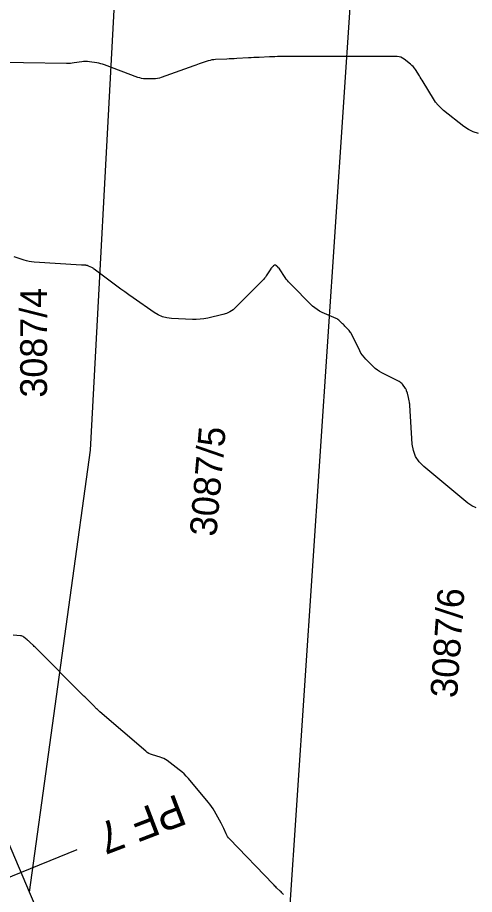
# Model space of a CAD drawing. Extents: x -534410 to -534262, y -1190162 to -1189584.
# Drawn here: x -534333.9 to -534319.42, y -1189974.68 to -1189946.91 of the extents above; entities that cross this region are included whole.
import ezdxf

# ---------------------------------------------------------------- set-up
doc = ezdxf.new("R2010")
doc.units = 0
for name, color, linetype in [('30', 7, 'Continuous'), ('31', 7, 'Continuous'), ('_N_text', 7, 'Continuous'), ('Hranice parcel', 7, 'Continuous'), ('Parcelní čísla', 7, 'Continuous')]:
    doc.layers.add(name, color=color, linetype=linetype)

msp = doc.modelspace()

# ---------------------------------------------------------------- linework, layer by layer
at = {"layer": '30'}
for points in [[(-534319.294, -1189950.581), (-534319.457, -1189950.53), (-534319.611, -1189950.455), (-534319.755, -1189950.356), (-534320.397, -1189949.847), (-534320.49, -1189949.766), (-534320.575, -1189949.678), (-534320.651, -1189949.583), (-534320.72, -1189949.48), (-534321.045, -1189948.943), (-534321.075, -1189948.894), (-534321.106, -1189948.845), (-534321.136, -1189948.796), (-534321.167, -1189948.747), (-534321.291, -1189948.552), (-534321.324, -1189948.505), (-534321.36, -1189948.461), (-534321.4, -1189948.42), (-534321.443, -1189948.382), (-534321.646, -1189948.221), (-534321.696, -1189948.187), (-534321.75, -1189948.163), (-534321.807, -1189948.148), (-534321.868, -1189948.144), (-534322.369, -1189948.144), (-534322.594, -1189948.144), (-534322.967, -1189948.144), (-534323.192, -1189948.144), (-534323.568, -1189948.144), (-534323.743, -1189948.144), (-534323.918, -1189948.144), (-534324.369, -1189948.144), (-534324.594, -1189948.144), (-534324.967, -1189948.144), (-534325.192, -1189948.144), (-534325.575, -1189948.144), (-534325.659, -1189948.144), (-534325.743, -1189948.146), (-534325.827, -1189948.148), (-534325.911, -1189948.151), (-534326.245, -1189948.167), (-534326.329, -1189948.171), (-534326.413, -1189948.175), (-534326.496, -1189948.179), (-534326.58, -1189948.184), (-534326.953, -1189948.204), (-534327.032, -1189948.208), (-534327.111, -1189948.212), (-534327.19, -1189948.216), (-534327.269, -1189948.22), (-534327.624, -1189948.237), (-534327.683, -1189948.241), (-534327.742, -1189948.25), (-534327.799, -1189948.263), (-534327.857, -1189948.279), (-534328.083, -1189948.354), (-534328.14, -1189948.372), (-534328.197, -1189948.392), (-534328.253, -1189948.411), (-534328.309, -1189948.431), (-534329.344, -1189948.802), (-534329.404, -1189948.821), (-534329.465, -1189948.834), (-534329.527, -1189948.842), (-534329.589, -1189948.845), (-534329.841, -1189948.845), (-534329.904, -1189948.842), (-534329.966, -1189948.834), (-534330.026, -1189948.82), (-534330.086, -1189948.801), (-534331.147, -1189948.405), (-534331.205, -1189948.386), (-534331.263, -1189948.369), (-534331.322, -1189948.355), (-534331.382, -1189948.344), (-534331.623, -1189948.306), (-534331.683, -1189948.299), (-534331.743, -1189948.297), (-534331.803, -1189948.299), (-534331.863, -1189948.306), (-534332.104, -1189948.344), (-534332.165, -1189948.352), (-534332.225, -1189948.358), (-534332.286, -1189948.361), (-534332.347, -1189948.361), (-534335.078, -1189948.316)], [(-534325.469, -1189974.679), (-534325.496, -1189974.652), (-534325.523, -1189974.624), (-534325.55, -1189974.597), (-534325.578, -1189974.571), (-534325.688, -1189974.463), (-534325.715, -1189974.436), (-534325.743, -1189974.409), (-534325.77, -1189974.382), (-534325.796, -1189974.354), (-534327.184, -1189972.912), (-534327.214, -1189972.877), (-534327.242, -1189972.84), (-534327.266, -1189972.801), (-534327.287, -1189972.759), (-534327.363, -1189972.588), (-534327.383, -1189972.546), (-534327.403, -1189972.504), (-534327.425, -1189972.462), (-534327.447, -1189972.421), (-534327.658, -1189972.04), (-534327.702, -1189971.964), (-534327.75, -1189971.89), (-534327.801, -1189971.819), (-534327.856, -1189971.75), (-534328.484, -1189970.999), (-534328.55, -1189970.924), (-534328.621, -1189970.853), (-534328.696, -1189970.787), (-534328.775, -1189970.724), (-534329.161, -1189970.438), (-534329.213, -1189970.403), (-534329.267, -1189970.373), (-534329.323, -1189970.348), (-534329.382, -1189970.327), (-534329.623, -1189970.256), (-534329.681, -1189970.235), (-534329.737, -1189970.209), (-534329.789, -1189970.176), (-534329.838, -1189970.138), (-534331.288, -1189968.891), (-534331.314, -1189968.867), (-534331.34, -1189968.843), (-534331.366, -1189968.819), (-534331.391, -1189968.794), (-534331.49, -1189968.692), (-534331.515, -1189968.666), (-534331.54, -1189968.641), (-534331.565, -1189968.616), (-534331.59, -1189968.591), (-534331.692, -1189968.492), (-534331.718, -1189968.468), (-534331.743, -1189968.443), (-534331.768, -1189968.418), (-534331.793, -1189968.393), (-534333.291, -1189966.895), (-534333.316, -1189966.87), (-534333.342, -1189966.845), (-534333.367, -1189966.82), (-534333.393, -1189966.795), (-534333.5, -1189966.691), (-534333.523, -1189966.67), (-534333.547, -1189966.648), (-534333.571, -1189966.628), (-534333.595, -1189966.608), (-534333.694, -1189966.529), (-534333.719, -1189966.511), (-534333.747, -1189966.498), (-534333.775, -1189966.488), (-534333.806, -1189966.483), (-534334.037, -1189966.462)]]:
    msp.add_lwpolyline(points, dxfattribs=at)
at = {"layer": '31'}
msp.add_lwpolyline([(-534319.367, -1189962.436), (-534319.505, -1189962.372), (-534319.633, -1189962.282), (-534321.029, -1189961.121), (-534321.176, -1189960.973), (-534321.286, -1189960.806), (-534321.357, -1189960.619), (-534321.39, -1189960.412), (-534321.468, -1189959.184), (-534321.471, -1189959.15), (-534321.475, -1189959.115), (-534321.481, -1189959.081), (-534321.488, -1189959.047), (-534321.524, -1189958.885), (-534321.529, -1189958.865), (-534321.534, -1189958.845), (-534321.54, -1189958.825), (-534321.546, -1189958.805), (-534321.571, -1189958.725), (-534321.578, -1189958.705), (-534321.586, -1189958.686), (-534321.596, -1189958.668), (-534321.608, -1189958.651), (-534321.703, -1189958.519), (-534321.724, -1189958.493), (-534321.748, -1189958.47), (-534321.775, -1189958.45), (-534321.804, -1189958.433), (-534322.355, -1189958.157), (-534322.428, -1189958.117), (-534322.497, -1189958.071), (-534322.563, -1189958.02), (-534322.624, -1189957.963), (-534322.862, -1189957.726), (-534322.919, -1189957.664), (-534322.97, -1189957.599), (-534323.016, -1189957.53), (-534323.056, -1189957.456), (-534323.332, -1189956.905), (-534323.348, -1189956.875), (-534323.366, -1189956.847), (-534323.387, -1189956.821), (-534323.409, -1189956.796), (-534323.503, -1189956.7), (-534323.527, -1189956.676), (-534323.55, -1189956.652), (-534323.574, -1189956.628), (-534323.598, -1189956.604), (-534323.695, -1189956.51), (-534323.72, -1189956.488), (-534323.746, -1189956.468), (-534323.775, -1189956.451), (-534323.805, -1189956.437), (-534324.249, -1189956.244), (-534324.33, -1189956.204), (-534324.407, -1189956.156), (-534324.48, -1189956.102), (-534324.547, -1189956.041), (-534325.269, -1189955.319), (-534325.309, -1189955.277), (-534325.346, -1189955.233), (-534325.382, -1189955.186), (-534325.415, -1189955.138), (-534325.593, -1189954.865), (-534325.6, -1189954.855), (-534325.608, -1189954.846), (-534325.616, -1189954.837), (-534325.625, -1189954.829), (-534325.666, -1189954.794), (-534325.673, -1189954.788), (-534325.681, -1189954.782), (-534325.688, -1189954.776), (-534325.696, -1189954.771), (-534325.728, -1189954.748), (-534325.735, -1189954.744), (-534325.743, -1189954.743), (-534325.75, -1189954.745), (-534325.758, -1189954.749), (-534325.787, -1189954.773), (-534325.795, -1189954.78), (-534325.802, -1189954.786), (-534325.809, -1189954.792), (-534325.816, -1189954.799), (-534325.848, -1189954.83), (-534325.856, -1189954.837), (-534325.862, -1189954.845), (-534325.869, -1189954.854), (-534325.875, -1189954.863), (-534326.016, -1189955.087), (-534326.042, -1189955.126), (-534326.07, -1189955.164), (-534326.101, -1189955.2), (-534326.134, -1189955.235), (-534326.979, -1189956.08), (-534327.07, -1189956.159), (-534327.169, -1189956.224), (-534327.276, -1189956.274), (-534327.392, -1189956.31), (-534327.871, -1189956.422), (-534327.991, -1189956.445), (-534328.112, -1189956.461), (-534328.233, -1189956.467), (-534328.356, -1189956.466), (-534329.017, -1189956.434), (-534329.164, -1189956.417), (-534329.305, -1189956.38), (-534329.439, -1189956.324), (-534329.567, -1189956.247), (-534330.239, -1189955.778), (-534330.367, -1189955.687), (-534330.495, -1189955.596), (-534330.622, -1189955.503), (-534330.748, -1189955.41), (-534331.468, -1189954.871), (-534331.486, -1189954.858), (-534331.505, -1189954.846), (-534331.524, -1189954.835), (-534331.544, -1189954.825), (-534331.646, -1189954.774), (-534331.655, -1189954.77), (-534331.664, -1189954.766), (-534331.674, -1189954.763), (-534331.684, -1189954.761), (-534331.723, -1189954.753), (-534331.733, -1189954.751), (-534331.743, -1189954.75), (-534331.753, -1189954.749), (-534331.763, -1189954.748), (-534331.832, -1189954.744), (-534331.869, -1189954.742), (-534333.372, -1189954.647), (-534333.453, -1189954.639), (-534333.533, -1189954.626), (-534333.612, -1189954.608), (-534333.691, -1189954.585), (-534334.001, -1189954.482)], dxfattribs=at)
at = {"layer": '_N_text'}
msp.add_lwpolyline([(-534332.014, -1189973.259), (-534343.129, -1189977.783)], dxfattribs=at)
at = {"layer": 'Hranice parcel'}
for p, q in [((-534326.36, -1189991.44), (-534323.33, -1189946.13)), ((-534333.52, -1189974.6), (-534336.09, -1189968.55)), ((-534326.36, -1189991.44), (-534333.52, -1189974.6))]:
    msp.add_line(p, q, dxfattribs=at)
msp.add_lwpolyline([(-534333.52, -1189974.6), (-534331.59, -1189960.61), (-534330.81, -1189946.26)], dxfattribs=at)

# ---------------------------------------------------------------- texts
at = {"layer": '_N_text'}
msp.add_text('PF 7', height=1, rotation=200.9666, dxfattribs=at).set_placement((-534328.83, -1189971.483))
at = {"layer": 'Parcelní čísla'}
for s, rotation, p in [('3087/4', 90, (-534332.964, -1189958.941)), ('3087/5', 85, (-534327.6, -1189963.36)), ('3087/6', 86, (-534319.974, -1189968.47))]:
    msp.add_text(s, height=0.85, rotation=rotation, dxfattribs=at).set_placement(p)

doc.saveas('drawing.dxf')
